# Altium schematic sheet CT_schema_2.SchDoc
size 386 x 209 mm
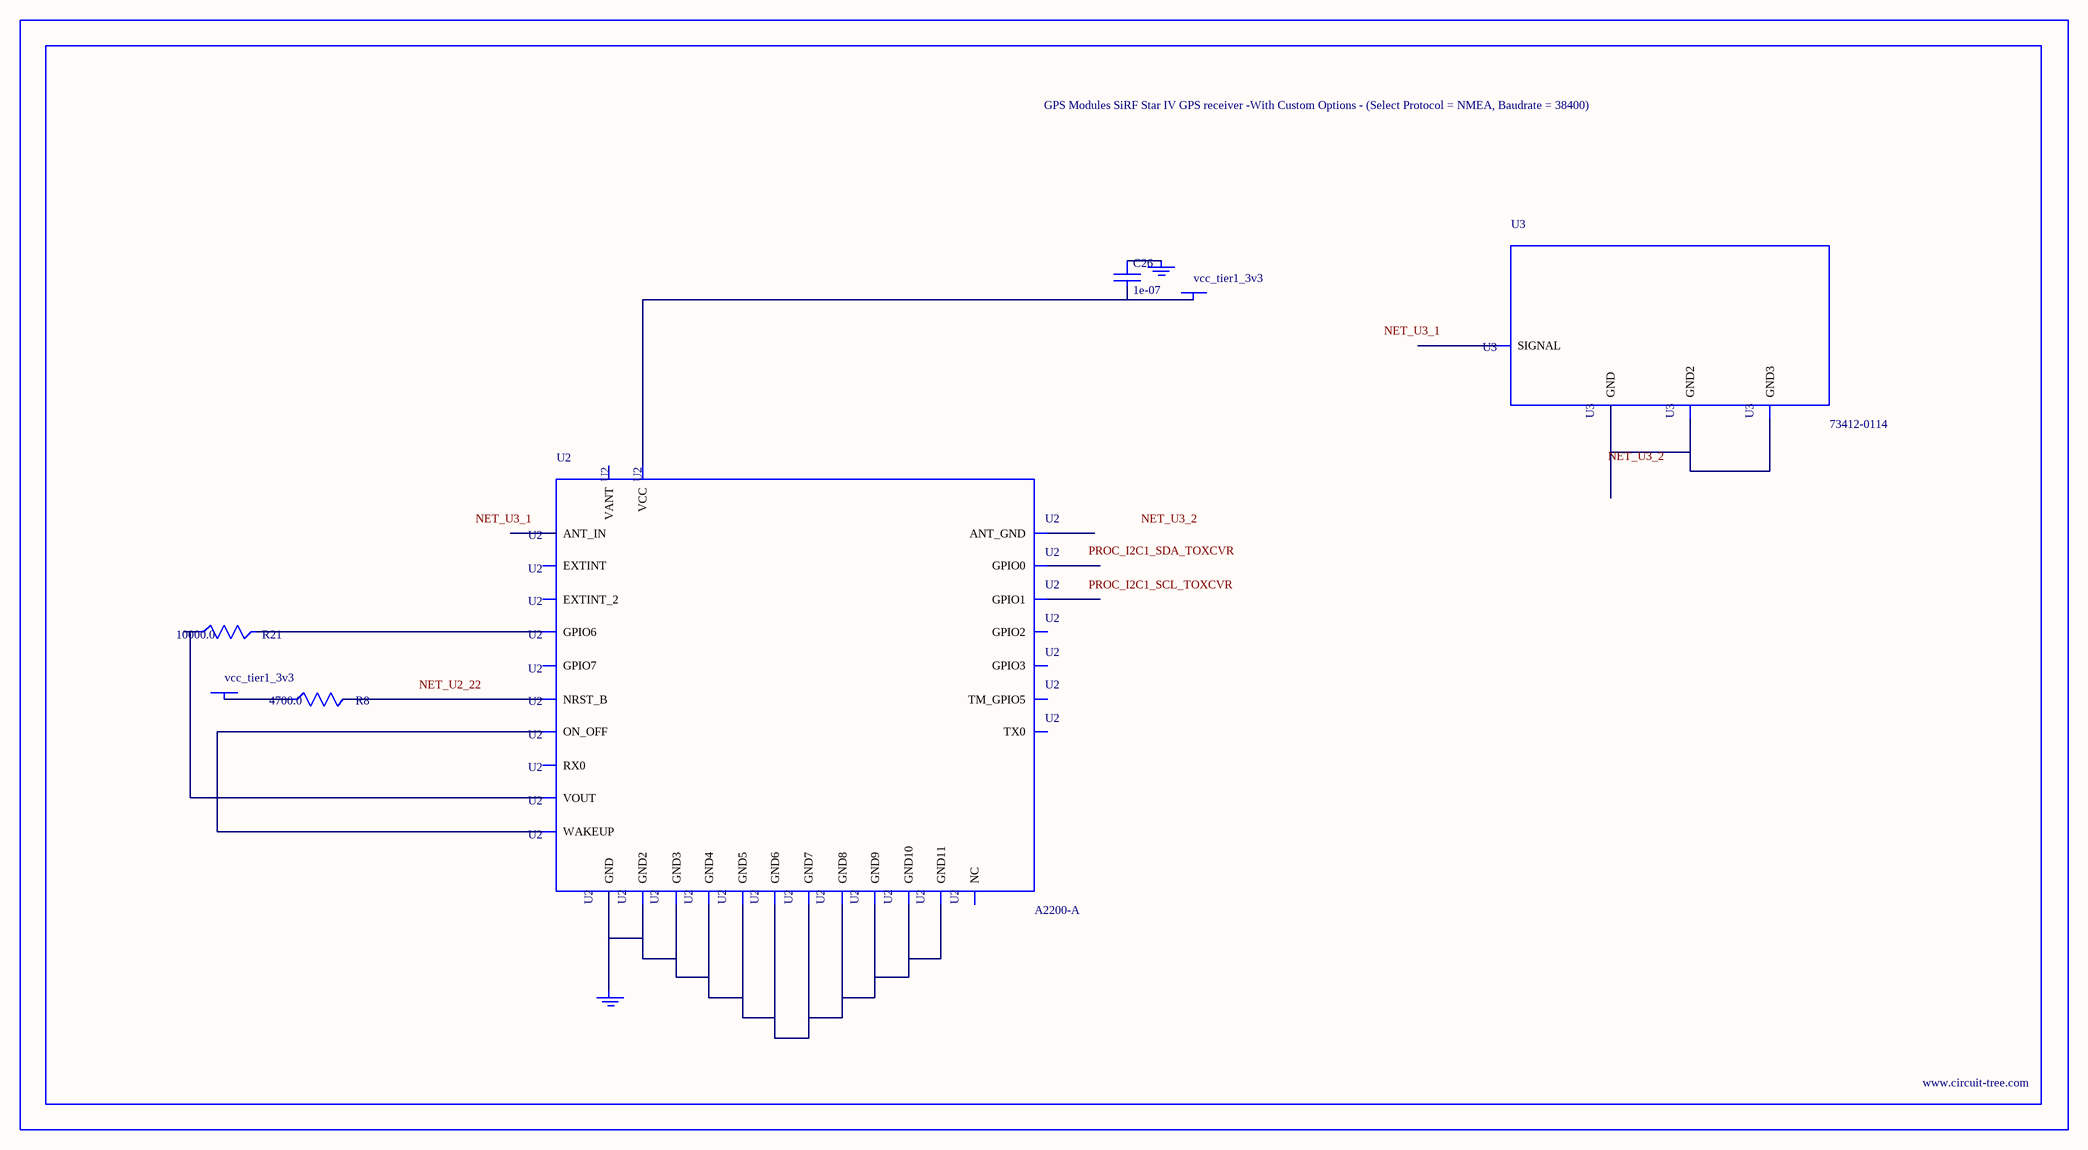
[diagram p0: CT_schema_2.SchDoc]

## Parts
BORDER1  (no value)
C26  1e-07  [C0402]
GND_INSTANCE_1_0  (no value)
GND_INSTANCE_1_1  (no value)
POWER_INSTANCE_1_0  vcc_tier1_3v3
POWER_INSTANCE_1_1  vcc_tier1_3v3
R8  4700.0  [R0603]
R21  10000.0  [R0603]
U2  A2200-A  [A2200-A]
U3  73412-0114  [COAXIAL_C]

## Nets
NetC26_1: C26.1 GND_INSTANCE_1_0.0(GND)
NetC26_2: C26.2 POWER_INSTANCE_1_0.0(PWR) U2.20(VCC)
NetGND_INSTANCE_1_1_0: GND_INSTANCE_1_1.0(GND) U2.7(GND) U2.8(GND2) U2.23(GND3) U2.24(GND4) U2.25(GND5) U2.26(GND6) U2.27(GND7) U2.28(GND8) U2.29(GND9) U2.30(GND10) U2.31(GND11)
NetPOWER_INSTANCE_1_1_0: POWER_INSTANCE_1_1.0(PWR) R8.1
NetR8_2: R8.2 U2.22(NRST_B)
NetR21_1: R21.1 U2.2(VOUT)
NetR21_2: R21.2 U2.17(GPIO6)
NetU2_6: U2.6(ON_OFF) U2.19(WAKEUP)
NetU3_2: U3.2(GND) U3.3(GND2) U3.4(GND3)

Not connected (* = marked no-connect by the designer): U2 1(GPIO2) 3(TX0) 4(RX0) 5(EXTINT_2) 9(VANT) 10(ANT_GND) 11(ANT_IN) 12(GPIO3) 13(EXTINT) 14(TM_GPIO5) 15(GPIO1) 16(GPIO0) 18(GPIO7) 21(NC); U3 1(SIGNAL)

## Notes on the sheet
- Labels drawn without touching a wire or pin: NET_U2_22, NET_U3_1, NET_U3_2, PROC_I2C1_SCL_TOXCVR, PROC_I2C1_SDA_TOXCVR

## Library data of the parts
BORDER1 = BORDER_PAGE1
C26 = C0402C104K3RACTU
GND_INSTANCE_1_0 GND_INSTANCE_1_1 = GND
POWER_INSTANCE_1_0 POWER_INSTANCE_1_1 = PWR
R8 = RC0603JR-074K7L
R21 = RC0603JR-0710KL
